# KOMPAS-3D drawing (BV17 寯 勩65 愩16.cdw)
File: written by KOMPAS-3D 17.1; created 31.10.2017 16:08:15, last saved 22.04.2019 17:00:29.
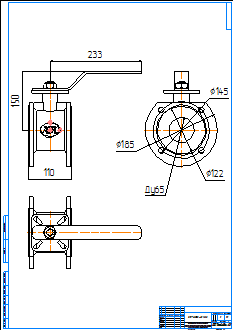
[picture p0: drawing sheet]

Sheet 1: A1, portrait

Title block, sheet 1: name: BV17 МФ Ду65 Ру16; material: Внимание! Данный продукт является объектом авторского права ООО «Торговый Дом АДЛ». / Запрещается изменение, копирование, распространение / (в том числе путем копирования на другие сайты и ресурсы в Интернете) / или любое иное использование информации и объектов без предварительного / согласия правообладателя (ООО «Торговый Дом АДЛ»).; mass: 1; sheets: 1; organisation: ООО "Торговый дом АДЛ"; sheet format: A1; stored path: \\adlc.lan\data\АДЛ_ПКД\3D-модели\ADL production\Краны шаровые серии BV\BV17 МФ Нержавеющие Ру16\KOMPAS 2D\BV17 МФ Ду65 Ру16.cdw

Views: Вид 1, Проекционный вид 2, Проекционный вид 3
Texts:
  kka
  adl
Dimensions and other numbers on the sheet: 110; 233; 150; 65; 185; 145; 122; 1:1; 1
